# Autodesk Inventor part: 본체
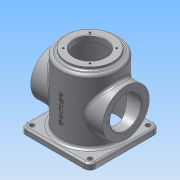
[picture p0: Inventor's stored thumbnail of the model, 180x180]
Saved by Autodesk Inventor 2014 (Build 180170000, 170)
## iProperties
Created: 2015-10
Part Number: 본체
Material: 알루미늄 6061
Document SubType Name: Modeling
Designer: net
Density: 2.71 g/cm^3
Appearance: 알루미늄 - 평지
Mass: 954.135 g
Surface Area: 1042.2 cm^2
Volume: 352.079 cm^3
Author: net
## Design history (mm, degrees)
sketch "스케치1"
  geometry: 1 further point
sketch "스케치2"
  geometry: L1 (60, 60)-(-60, 60); L2 (-60, 60)-(-60, -60); L3 (-60, -60)-(60, -60); L4 (60, -60)-(60, 60); L5 (60, 60)-(-60, -60); L6 (-60, 60)-(60, -60); 1 further point
  constraints: 12 end point, 2 midpoint, 2 parallel, 1 horizontal, 1 perpendicular
  dimensions: "d0" = 120 distance of L3.end L2.end; "d1" = 120 distance between parallel lines of L3 L1
extrude "돌출1" new body sketch "스케치2" distance "d2" = 10; taper "d3" = 0 deg
sketch "스케치4"
  geometry: L1 (-60, 0)-(60, 0) reference; L2 (-60, 0)-(-60, 10) reference; L3 (60, 0)-(60, 10) reference; L4 (-60, 10)-(60, 10) reference; L5 (0, 0)-(0, 120); L6 (0, 120)-(-50, 120); L7 (-50, 120)-(-50, 0); L8 (-45, 0)-(-45, 115); L9 (-45, 115)-(0, 115); L10 (-45, 0)-(0, 0); 1 further point
  constraints: 12 end point, 3 point on line, 2 horizontal, 2 midpoint, 1 parallel, 1 vertical
  dimensions: "d10" = 50 distance between parallel lines of L5 L7; "d11" = 5 distance between parallel lines of L8 L7; "d16" = 120 distance between parallel lines of L1 L6; "d17" = 5 distance between parallel lines of L9 L6; "d18" = 10 distance from line of L8.start L4
revolve "회전2" stored, may be unused: angle "d19" = 90 deg
revolve "회전3" stored, may be unused: angle "d20" = 90 deg
sketch "스케치5"
  geometry: C1 r 40 at (0, 0); C2 r 27 at (0, 0); C3 r 50 at (0, 0) reference; C4 r 27 at (0, 0); 1 further point
  constraints: 3 centre point, 3 coincident, 1 concentric
  dimensions: "d21" = 80 diameter of C1; "d22" = 54 diameter of C2
extrude "돌출2" join sketch "스케치5" distance "d23" = 5; taper "d24" = 0 deg
node "작업 평면2"
sketch "스케치8"
  geometry: L1 (50, 120)-(-50, 120) reference; L2 (-50, 10)-(50, 10) reference; L3 (-60, 0)-(60, 0) reference; L4 (-60, 0)-(60, 0) reference; L5 (60, 0)-(60, 10) reference; L6 (-60, 10)-(60, 10) reference; L7 (-60, 0)-(-60, 10) reference; C1 r 40 at (0, 60); C2 r 27 at (0, 60); 2 further points
  constraints: 2 centre point, 1 coincident, 1 midpoint, 1 vertical alignment
  dimensions: "d51" = 80 diameter of C1; "d52" = 54 diameter of C2; "d53" = 60 distance of point (0, 0) C1.centre
  node "투영된 루프3"
  node "투영된 루프4"
extrude "돌출6" join sketch "스케치8" stored distance "d54" = 5; taper "d55" = 0 deg
extrude "돌출7" cut sketch "스케치8" stored distance "d56" = 5; taper "d57" = 0 deg
sketch "스케치9"
  geometry: C1 r 27 at (0, 0) reference; C2 r 27 at (0, 0)
  constraints: 1 centre point, 1 coincident
  dimensions: "d58" = 54 diameter of C2
extrude "돌출8" cut sketch "스케치9" stored distance "d59" = 5; taper "d60" = 0 deg
sketch "스케치10"
  geometry: C1 r 27 at (0, 0) reference; 2 further points
  constraints: 1 horizontal alignment
  dimensions: "d61" = 45 deg dimension on C1.centre point (22.981, -22.981) point (33.702, 0); "d62" = 32.5 distance of C1.centre point (22.981, -22.981)
hole "구멍2" sketch "스케치10" at (22.981, -22.981) diameter "d63" = 3.242; stored, may be unused: countersink angle "d67" = 90 deg, drill point angle "d69" = 118 deg; dims "d64" = 8, "d65" = 4, "d66" = 2, "d68" = 10
sketch "스케치11"
  geometry: C1 r 27 at (0, 0) reference; 2 further points
  constraints: 1 horizontal alignment
  dimensions: "d73" = 32.5 distance of C1.centre point (-32.5, 0)
hole "구멍3" sketch "스케치11" at (-32.5, 0) diameter "d74" = 3.242; stored, may be unused: countersink angle "d78" = 90 deg, drill point angle "d80" = 118 deg; dims "d75" = 8, "d76" = 4, "d77" = 2, "d79" = 10
hole "구멍4" diameter "d86" = 8; stored, may be unused: countersink angle "d90" = 90 deg, drill point angle "d92" = 0 deg; dims "d84" = 10, "d85" = 10, "d87" = 8, "d88" = 4, "d89" = 2, "d91" = 10
fillet "모깎기1" dims "d99" = 10
fillet "모깎기2" dims "d100" = 5
fillet "모깎기3" dims "d101" = 5
fillet "모깎기4" dims "d102" = 5
fillet "모깎기5" dims "d103" = 5
fillet "모깎기6" dims "d104" = 3
fillet "모깎기7" dims "d105" = 3
chamfer "모따기1" distance "d106" = 3; stored, may be unused: second distance "d107" = 2, angle "d108" = 45 deg
chamfer "모따기2" distance "d109" = 1; stored, may be unused: second distance "d110" = 2, angle "d111" = 45 deg
chamfer "모따기3" distance "d112" = 1; stored, may be unused: second distance "d113" = 2, angle "d114" = 45 deg
node "작업 평면3"
sketch "스케치12"
  geometry: L1 (-48, -60)-(48, -60) reference; L2 (-62, 40)-(-62, -40) reference; 2 further points
  constraints: 1 other
feature "엠보싱1" sketch "스케치12" dims "d0" = 120, "d1" = 120, "d115" = 0.5, "d116" = 0
node "작업 평면1"
sketch "스케치6"
  geometry: L1 (50, 120)-(-50, 120) reference; L2 (-50, 10)-(50, 10) reference; C1 r 40 at (0, 60); C2 r 27 at (0, 60); 1 further point
  constraints: 2 centre point, 1 coincident, 1 vertical alignment
  dimensions: "d26" = 80 diameter of C1; "d27" = 54 diameter of C2; "d28" = 60 distance of point (0, 0) C1.centre
  node "투영된 루프2"
extrude "돌출3" join sketch "스케치6" stored distance "d29" = 5; taper "d30" = 0 deg
extrude "돌출4" cut sketch "스케치6" stored distance "d31" = 5; taper "d32" = 0 deg
extrude "돌출5" cut sketch "스케치5" stored distance "d33" = 5; taper "d34" = 0 deg
hole "구멍1" diameter "d37" = 8; stored, may be unused: countersink angle "d41" = 90 deg, drill point angle "d43" = 0 deg; dims "d35" = 10, "d36" = 10, "d38" = 6, "d39" = 4, "d40" = 2, "d42" = 8
sketch "스케치7"
  geometry: C1 r 27 at (0, 0) reference; C2 r 40 at (0, 0) reference
node "솔리드1"
mirror "대칭4"
pattern_circular "원형 패턴1" dims angle "d71" = 360 deg
pattern_circular "원형 패턴2" dims angle "d82" = 360 deg
mirror "대칭5"
pattern_linear "직사각형 패턴2" dims "d95" = 100
mirror "대칭3"
pattern_linear "직사각형 패턴1" dims "d46" = 100
mirror "대칭1"
mirror "대칭2"
other parameters: "d25" = 62.5, "d50" = 62
